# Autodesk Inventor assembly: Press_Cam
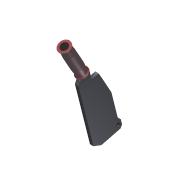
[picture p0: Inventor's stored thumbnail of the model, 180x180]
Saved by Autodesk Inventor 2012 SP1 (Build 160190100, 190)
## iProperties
Created: 2005-12
Part Number: Press_Cam
Document SubType Name: Assembly
Designer: t_munrn
Author: t_munrn
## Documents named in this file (3)
- D:\AOTC\Autodesk Inventor 2012 Essential for New Users\Autodesk Inventor 2012 Essentials - Project Files\Learning\Workspace\Sub-Assemblies\Press_Cam.iam
- D:\AOTC\Autodesk Inventor 2012 Essential for New Users\Autodesk Inventor 2012 Essentials - Project Files\Learning\Workspace\Sub-Assemblies\Handle1.iam
- D:\AOTC\Autodesk Inventor 2012 Essential for New Users\Autodesk Inventor 2012 Essentials - Project Files\Learning\Workspace\Parts\Press_Cam.ipt
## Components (2 placed, 2 different names)
1. Handle:1 [sub-assembly]
2. Press_Cam:1
